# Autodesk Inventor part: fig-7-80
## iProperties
Created: 2005-04
Part Number: fig-7-80
Document SubType Name: Modeling
Designer: MYPC
Author: MYPC
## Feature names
1. Extrusion1
2. Key Round (Hole)1 [Extrusion]
